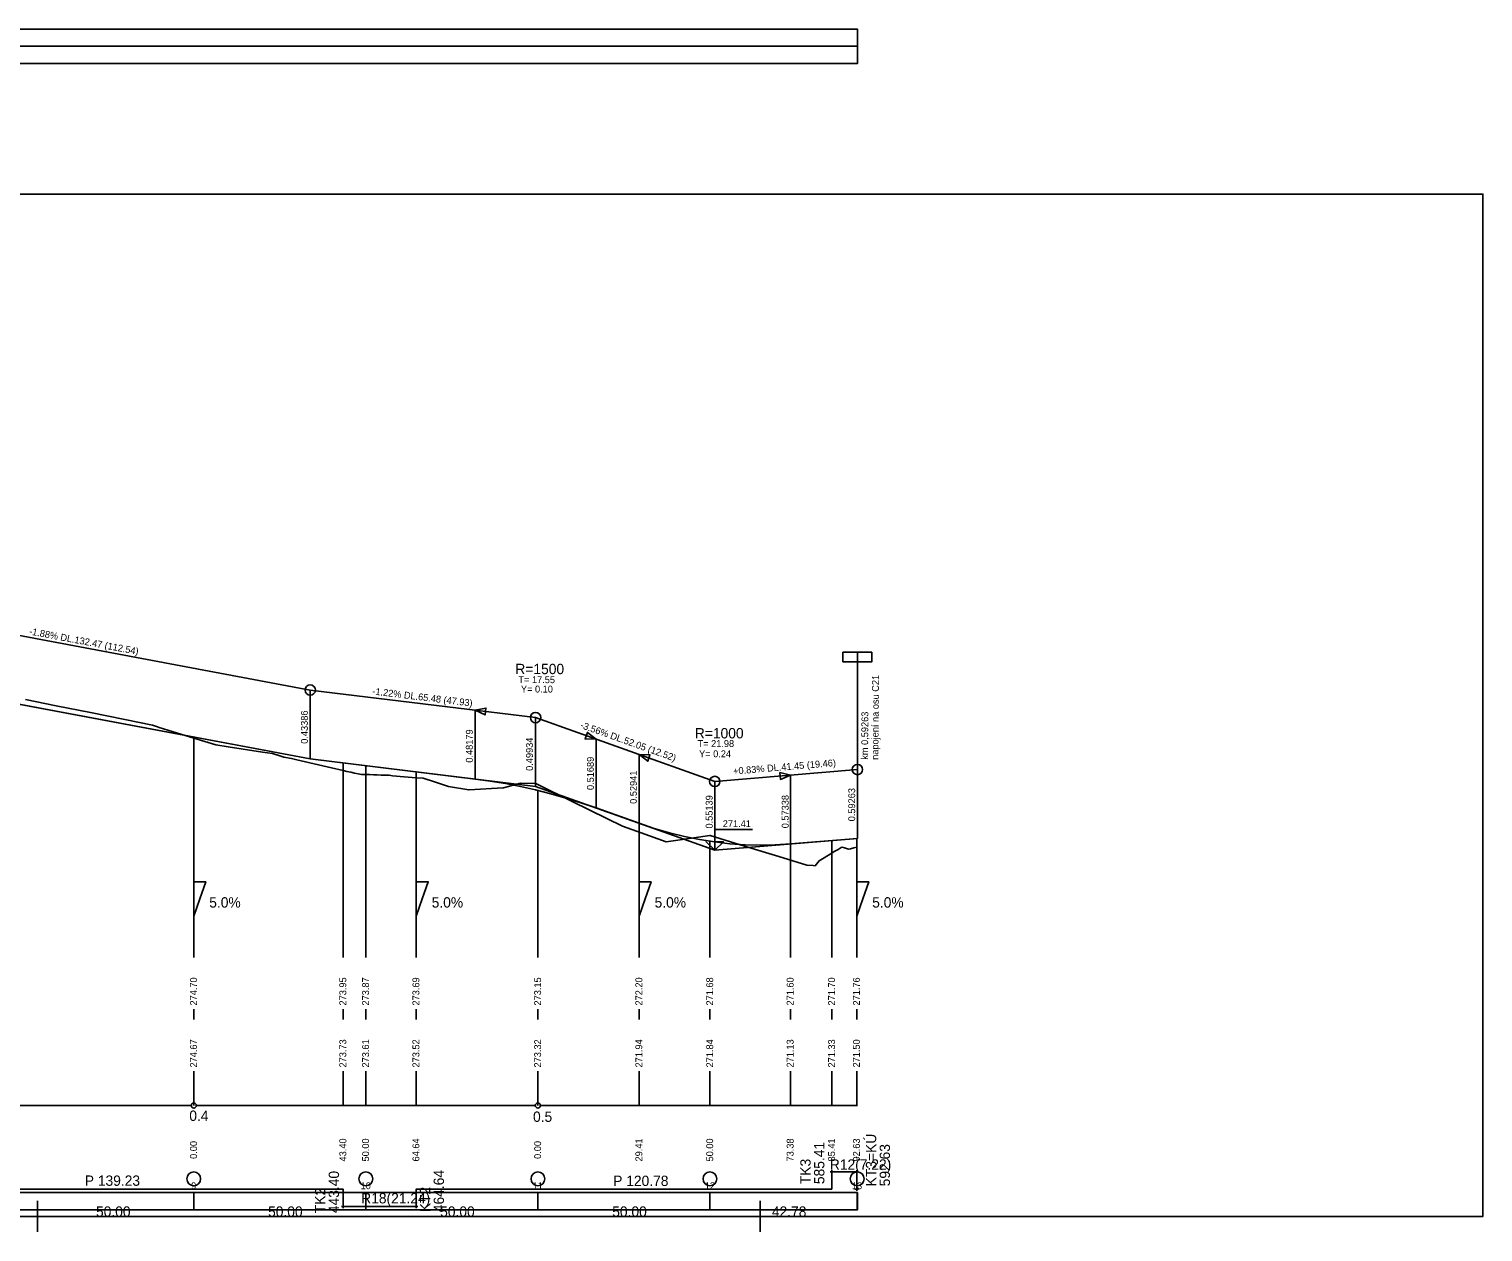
# Model space of a CAD drawing. Extents: x 775.4 to 859.4, y 113.2 to 148.1.
# Drawn here: x 817.16 to 859.41, y 113.16 to 148.1 of the extents above; entities that cross this region are included whole.
import ezdxf

# ---------------------------------------------------------------- set-up
doc = ezdxf.new("R2010")
doc.units = 0
for name, color, linetype in [('KOTA', 7, 'Continuous'), ('NOVY_STAV', 7, 'Continuous'), ('NS_OBLOUK', 7, 'Continuous'), ('REZY_PO', 7, 'Continuous'), ('SESTAVY_REZU_PO', 7, 'Continuous'), ('SKLONOVE_POMERY', 7, 'Continuous'), ('SMEROVE_POMERY', 7, 'Continuous'), ('SMEROVE_POMERY_KOD', 7, 'Continuous'), ('SVK_STAT', 7, 'Continuous'), ('TABULKY', 7, 'Continuous'), ('u_pricne_rezy', 7, 'Continuous'), ('x_formát_rám', 7, 'Continuous')]:
    doc.layers.add(name, color=color, linetype=linetype)

msp = doc.modelspace()

# ---------------------------------------------------------------- linework, layer by layer
at = {"layer": 'KOTA'}
for points in [[(837.086, 124.243), (836.836, 124.493), (837.086, 124.243), (837.086, 124.843), (838.186, 124.843)], [(837.086, 124.493), (837.086, 124.243), (837.336, 124.493), (837.086, 124.493)], [(837.086, 124.243), (837.336, 124.493), (837.086, 124.493)], [(837.086, 124.243), (837.086, 124.243)]]:
    msp.add_lwpolyline(points, dxfattribs=at)
at = {"layer": 'NOVY_STAV'}
msp.add_line((841.231, 126.589), (841.231, 129.721), dxfattribs=at)
for points in [[(781.947, 140.059), (784.712, 138.473), (794.036, 135.647), (812.086, 129.383), (825.333, 126.899), (831.881, 126.098), (837.086, 124.243), (841.231, 124.589)], [(812.086, 131.383), (825.333, 128.899)], [(814.079, 129.01), (825.333, 126.899), (830.127, 126.313), (830.565, 126.253), (831.004, 126.18), (831.443, 126.094), (831.881, 125.995), (832.32, 125.884), (832.759, 125.76), (833.197, 125.623), (833.636, 125.473), (834.888, 125.027), (835.328, 124.88), (835.767, 124.752), (836.207, 124.644), (836.647, 124.555), (837.086, 124.485), (837.526, 124.435), (837.966, 124.404), (838.405, 124.392), (838.845, 124.4), (839.285, 124.427), (841.231, 124.589)], [(825.333, 126.899), (825.333, 128.899)], [(825.333, 128.899), (831.881, 128.098)], [(831.881, 126.098), (831.881, 128.098)], [(831.881, 128.098), (837.086, 126.243)], [(837.086, 126.243), (841.231, 126.589)], [(841.231, 124.589), (841.231, 126.589)], [(837.086, 124.243), (837.086, 126.243)]]:
    msp.add_lwpolyline(points, dxfattribs=at)
for points in [[(840.811, 130.001), (841.231, 130.001), (841.231, 129.721), (840.811, 129.721)], [(841.651, 130.001), (841.231, 130.001), (841.231, 129.721), (841.651, 129.721)]]:
    msp.add_lwpolyline(points, close=True, dxfattribs=at)
for centre in [(825.333, 128.899), (831.881, 128.098), (841.231, 126.589), (837.086, 126.243)]:
    msp.add_circle(centre, 0.15, dxfattribs=at)
at = {"layer": 'NS_OBLOUK'}
for points in [[(830.127, 128.313), (830.412, 128.177), (830.436, 128.375), (830.127, 128.313)], [(830.127, 126.313), (830.127, 128.313)], [(833.32, 127.479), (833.636, 127.473), (833.387, 127.668), (833.32, 127.479)], [(833.636, 125.473), (833.636, 127.473)], [(834.888, 125.027), (834.888, 127.027)], [(834.888, 127.027), (835.137, 126.832), (835.204, 127.02), (834.888, 127.027)], [(838.994, 126.302), (839.285, 126.427), (838.978, 126.501), (838.994, 126.302)], [(839.285, 124.427), (839.285, 126.427)]]:
    msp.add_lwpolyline(points, dxfattribs=at)
for points in [[(830.127, 128.313), (830.436, 128.375), (830.412, 128.177)], [(833.636, 127.473), (833.387, 127.668), (833.32, 127.479)], [(834.888, 127.027), (835.204, 127.02), (835.137, 126.832)], [(839.285, 126.427), (838.978, 126.501), (838.994, 126.302)]]:
    msp.add_lwpolyline(points, close=True, dxfattribs=at)
at = {"layer": 'REZY_PO'}
msp.add_lwpolyline([(817.059, 128.623), (817.947, 128.443), (818.947, 128.241), (819.947, 128.039), (820.751, 127.877), (820.892, 127.828), (820.947, 127.811), (821.947, 127.503), (821.947, 127.503), (822.59, 127.305), (822.947, 127.25), (823.947, 127.095), (824.233, 127.051), (824.448, 126.99), (824.566, 126.947), (824.789, 126.905), (824.947, 126.869), (825.947, 126.639), (826.287, 126.56), (826.287, 126.56), (826.287, 126.56), (826.397, 126.535), (826.507, 126.511), (826.617, 126.488), (826.727, 126.465), (826.819, 126.447), (826.837, 126.447), (826.947, 126.444), (827.058, 126.44), (827.169, 126.437), (827.281, 126.433), (827.392, 126.429), (827.503, 126.425), (827.614, 126.421), (827.629, 126.421), (827.725, 126.41), (827.836, 126.397), (827.947, 126.386), (828.063, 126.376), (828.179, 126.366), (828.295, 126.357), (828.411, 126.35), (828.411, 126.35), (828.411, 126.35), (828.613, 126.338), (828.947, 126.229), (829.347, 126.099), (829.936, 125.998), (829.947, 125.999), (830.925, 126.054), (830.947, 126.06), (831.44, 126.193), (831.883, 126.183), (831.947, 126.152), (832.947, 125.66), (833.947, 125.168), (834.41, 124.94), (834.947, 124.748), (835.676, 124.487), (835.947, 124.526), (836.947, 124.668), (836.957, 124.669), (837.947, 124.366), (838.947, 124.06), (839.757, 123.812), (839.947, 123.799), (840.002, 123.796), (840.119, 123.94), (840.488, 124.161), (840.488, 124.161), (840.488, 124.161), (840.558, 124.204), (840.58, 124.215), (840.672, 124.267), (840.764, 124.322), (840.784, 124.335), (840.855, 124.312), (840.947, 124.282), (840.971, 124.274), (841.035, 124.289), (841.123, 124.311), (841.211, 124.332), (841.211, 124.332), (841.211, 124.332), (841.225, 124.336)], dxfattribs=at)
at = {"layer": 'SESTAVY_REZU_PO'}
for points in [[(812.022, 116.829), (821.872, 116.829)], [(822.022, 116.829), (831.872, 116.829)], [(832.022, 116.829), (841.231, 116.829)]]:
    msp.add_lwpolyline(points, dxfattribs=at)
for centre in [(821.947, 116.829), (831.947, 116.829)]:
    msp.add_circle(centre, 0.075, dxfattribs=at)
at = {"layer": 'SKLONOVE_POMERY'}
for points in [[(821.947, 123.329), (821.947, 122.329), (821.947, 122.329), (822.122, 122.829), (822.297, 123.329), (821.947, 123.329)], [(828.411, 123.329), (828.411, 122.329), (828.411, 122.329), (828.586, 122.829), (828.761, 123.329), (828.411, 123.329)], [(834.888, 123.329), (834.888, 122.329), (834.888, 122.329), (835.063, 122.829), (835.238, 123.329), (834.888, 123.329)], [(841.211, 123.329), (841.211, 122.329), (841.211, 122.329), (841.386, 122.829), (841.561, 123.329), (841.211, 123.329)]]:
    msp.add_lwpolyline(points, dxfattribs=at)
at = {"layer": 'SMEROVE_POMERY'}
msp.add_lwpolyline([(781.947, 114.399), (810.428, 114.399), (810.428, 114.899), (812.364, 114.899), (812.364, 114.399), (826.287, 114.399), (826.287, 113.899), (828.411, 113.899), (828.411, 114.399), (840.488, 114.399), (840.488, 114.899), (841.211, 114.899), (841.211, 114.399), (841.225, 114.399)], dxfattribs=at)
at = {"layer": 'SMEROVE_POMERY_KOD'}
for points in [[(840.488, 114.849), (840.488, 114.949)], [(841.211, 114.849), (841.211, 114.949)], [(840.438, 114.899), (840.538, 114.899)], [(841.161, 114.899), (841.261, 114.899)], [(841.161, 114.399), (841.261, 114.399)], [(841.211, 114.349), (841.211, 114.449)], [(826.237, 113.899), (826.337, 113.899)], [(826.287, 113.849), (826.287, 113.949)], [(828.361, 113.899), (828.461, 113.899)], [(828.411, 113.849), (828.411, 113.949)]]:
    msp.add_lwpolyline(points, dxfattribs=at)
at = {"layer": 'SVK_STAT'}
for points in [[(821.947, 121.129), (821.947, 127.534)], [(826.287, 121.129), (826.287, 126.782)], [(826.947, 121.129), (826.947, 126.701)], [(828.411, 121.129), (828.411, 126.522)], [(831.947, 121.129), (831.947, 125.979)], [(834.888, 121.129), (834.888, 125.027)], [(836.947, 121.129), (836.947, 124.507)], [(839.285, 121.129), (839.285, 124.427)], [(840.488, 121.129), (840.488, 124.527)], [(841.211, 121.129), (841.211, 124.587)], [(821.947, 119.329), (821.947, 119.629)], [(826.287, 119.329), (826.287, 119.629)], [(826.947, 119.329), (826.947, 119.629)], [(828.411, 119.329), (828.411, 119.629)], [(831.947, 119.329), (831.947, 119.629)], [(834.888, 119.329), (834.888, 119.629)], [(836.947, 119.329), (836.947, 119.629)], [(839.285, 119.329), (839.285, 119.629)], [(840.488, 119.329), (840.488, 119.629)], [(841.211, 119.329), (841.211, 119.629)], [(821.947, 116.829), (821.947, 117.829)], [(826.287, 116.829), (826.287, 117.829)], [(826.947, 116.829), (826.947, 117.829)], [(828.411, 116.829), (828.411, 117.829)], [(831.947, 116.829), (831.947, 117.829)], [(834.888, 116.829), (834.888, 117.829)], [(836.947, 116.829), (836.947, 117.829)], [(839.285, 116.829), (839.285, 117.829)], [(840.488, 116.829), (840.488, 117.829)], [(841.211, 116.829), (841.211, 117.829)]]:
    msp.add_lwpolyline(points, dxfattribs=at)
at = {"layer": 'TABULKY'}
for points in [[(781.947, 147.099), (841.231, 147.099), (841.231, 148.099), (781.947, 148.099), (781.947, 147.099)], [(781.947, 147.599), (841.231, 147.599)]]:
    msp.add_lwpolyline(points, dxfattribs=at)
at = {"layer": 'u_pricne_rezy'}
for points in [[(781.947, 113.798), (841.231, 113.798), (841.231, 114.298), (781.947, 114.298), (781.947, 113.798)], [(821.947, 113.798), (821.947, 114.298)], [(826.947, 113.798), (826.947, 114.298)], [(831.947, 113.798), (831.947, 114.298)], [(836.947, 113.798), (836.947, 114.298)], [(841.225, 113.798), (841.225, 114.298)]]:
    msp.add_lwpolyline(points, dxfattribs=at)
for centre in [(821.947, 114.698), (826.947, 114.698), (831.947, 114.698), (836.947, 114.698), (841.225, 114.698)]:
    msp.add_circle(centre, 0.2, dxfattribs=at)
at = {"layer": 'x_formát_rám'}
for p, q in [((817.407, 113.157), (817.407, 114.057)), ((838.407, 113.157), (838.407, 114.057))]:
    msp.add_line(p, q, dxfattribs=at)
msp.add_lwpolyline([(775.407, 113.607), (859.407, 113.607), (859.407, 143.307), (775.407, 143.307)], close=True, dxfattribs=at)

# ---------------------------------------------------------------- texts
at = {"layer": 'KOTA'}
msp.add_text('271.41', height=0.2, dxfattribs=at).set_placement((837.319, 124.915))
at = {"layer": 'NOVY_STAV'}
for s, rotation, p in [('-1.88% DL.132.47 (112.54)', 349.3778, (817.153, 130.514)), ('napojení na osu C21', 89.5404, (841.839, 126.87)), ('-1.22% DL.65.48 (47.93)', 353.0266, (827.129, 128.771)), (' 0.43386', 90, (825.262, 127.263)), ('km 0,59263', 89.5404, (841.539, 126.872)), ('-3.56% DL.52.05 (12.52)', 340.3898, (833.161, 127.802)), (' 0.49934', 90, (831.802, 126.476)), ('+0.83% DL.41.45 (19.46)', 4.7663, (837.628, 126.442)), (' 0.59263', 90, (841.166, 125.01)), (' 0.55139', 90, (837.024, 124.801))]:
    msp.add_text(s, height=0.2, rotation=rotation, dxfattribs=at).set_placement(p)
at = {"layer": 'NS_OBLOUK'}
for s, height, p in [('R=1500', 0.3, (831.292, 129.36)), ('T= 17.55', 0.2, (831.381, 129.098)), ('Y= 0.10', 0.2, (831.454, 128.826)), ('R=1000', 0.3, (836.508, 127.494)), ('T= 21.98', 0.2, (836.586, 127.243)), ('Y= 0.24', 0.2, (836.631, 126.946))]:
    msp.add_text(s, height=height, dxfattribs=at).set_placement(p)
for s, p in [(' 0.48179', (830.054, 126.714)), (' 0.51689', (833.573, 125.919)), (' 0.52941', (834.822, 125.517)), (' 0.57338', (839.233, 124.808))]:
    msp.add_text(s, height=0.2, rotation=90, dxfattribs=at).set_placement(p)
at = {"layer": 'SESTAVY_REZU_PO'}
for s, p in [('0.4', (821.818, 116.382)), ('0.5', (831.806, 116.354))]:
    msp.add_text(s, height=0.3, dxfattribs=at).set_placement(p)
at = {"layer": 'SKLONOVE_POMERY'}
for p in [(822.397, 122.579), (828.861, 122.579), (835.338, 122.579), (841.661, 122.579)]:
    msp.add_text('5.0%', height=0.3, dxfattribs=at).set_placement(p)
at = {"layer": 'SMEROVE_POMERY'}
for s, p in [('R12(7.22)', (840.431, 114.965)), ('P 139.23', (818.781, 114.496)), ('P 120.78', (834.135, 114.491)), ('R18(21.24)', (826.813, 113.985))]:
    msp.add_text(s, height=0.3, dxfattribs=at).set_placement(p)
at = {"layer": 'SMEROVE_POMERY_KOD'}
for s, p in [('585.41', (840.272, 114.545)), ('KT3=KÚ', (841.778, 114.481)), ('592.63', (842.178, 114.481)), ('443.40', (826.169, 113.702)), ('464.64', (829.218, 113.73)), ('TK3', (839.872, 114.545)), ('TK2', (825.769, 113.702)), ('KT2', (828.818, 113.73))]:
    msp.add_text(s, height=0.3, rotation=90, dxfattribs=at).set_placement(p)
at = {"layer": 'SVK_STAT'}
for s, p in [(' 274.70', (822.04, 119.659)), (' 273.95', (826.379, 119.659)), (' 273.87', (827.04, 119.659)), (' 273.69', (828.503, 119.659)), (' 273.15', (832.04, 119.659)), (' 272.20', (834.981, 119.659)), (' 271.68', (837.04, 119.659)), (' 271.60', (839.377, 119.659)), (' 271.70', (840.581, 119.659)), (' 271.76', (841.303, 119.659)), (' 274.67', (822.04, 117.859)), (' 273.73', (826.379, 117.859)), (' 273.61', (827.04, 117.859)), (' 273.52', (828.503, 117.859)), (' 273.32', (832.04, 117.859)), (' 271.94', (834.981, 117.859)), (' 271.84', (837.04, 117.859)), (' 271.13', (839.377, 117.859)), (' 271.33', (840.581, 117.859)), (' 271.50', (841.303, 117.859)), ('  0.00', (822.04, 115.129)), (' 43.40', (826.379, 115.129)), (' 50.00', (827.04, 115.129)), (' 64.64', (828.503, 115.129)), ('  0.00', (832.04, 115.129)), (' 29.41', (834.981, 115.129)), (' 50.00', (837.04, 115.129)), (' 73.38', (839.377, 115.129)), (' 85.41', (840.581, 115.129)), (' 92.63', (841.303, 115.129))]:
    msp.add_text(s, height=0.2, rotation=90, dxfattribs=at).set_placement(p)
at = {"layer": 'u_pricne_rezy'}
for s, height, p in [('9', 0.2, (821.872, 114.398)), ('10', 0.2, (826.796, 114.398)), ('11', 0.2, (831.796, 114.398)), ('12', 0.2, (836.796, 114.398)), ('13', 0.2, (841.074, 114.398)), ('50.00', 0.3, (819.107, 113.598)), ('50.00', 0.3, (824.107, 113.598)), ('50.00', 0.3, (829.107, 113.598)), ('50.00', 0.3, (834.107, 113.598)), ('42.78', 0.3, (838.746, 113.598))]:
    msp.add_text(s, height=height, dxfattribs=at).set_placement(p)

doc.saveas('drawing.dxf')
